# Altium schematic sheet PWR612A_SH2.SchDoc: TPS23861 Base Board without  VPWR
size 558 x 431 mm; Engineer: Trevor; Revision: A; Name: Trevor
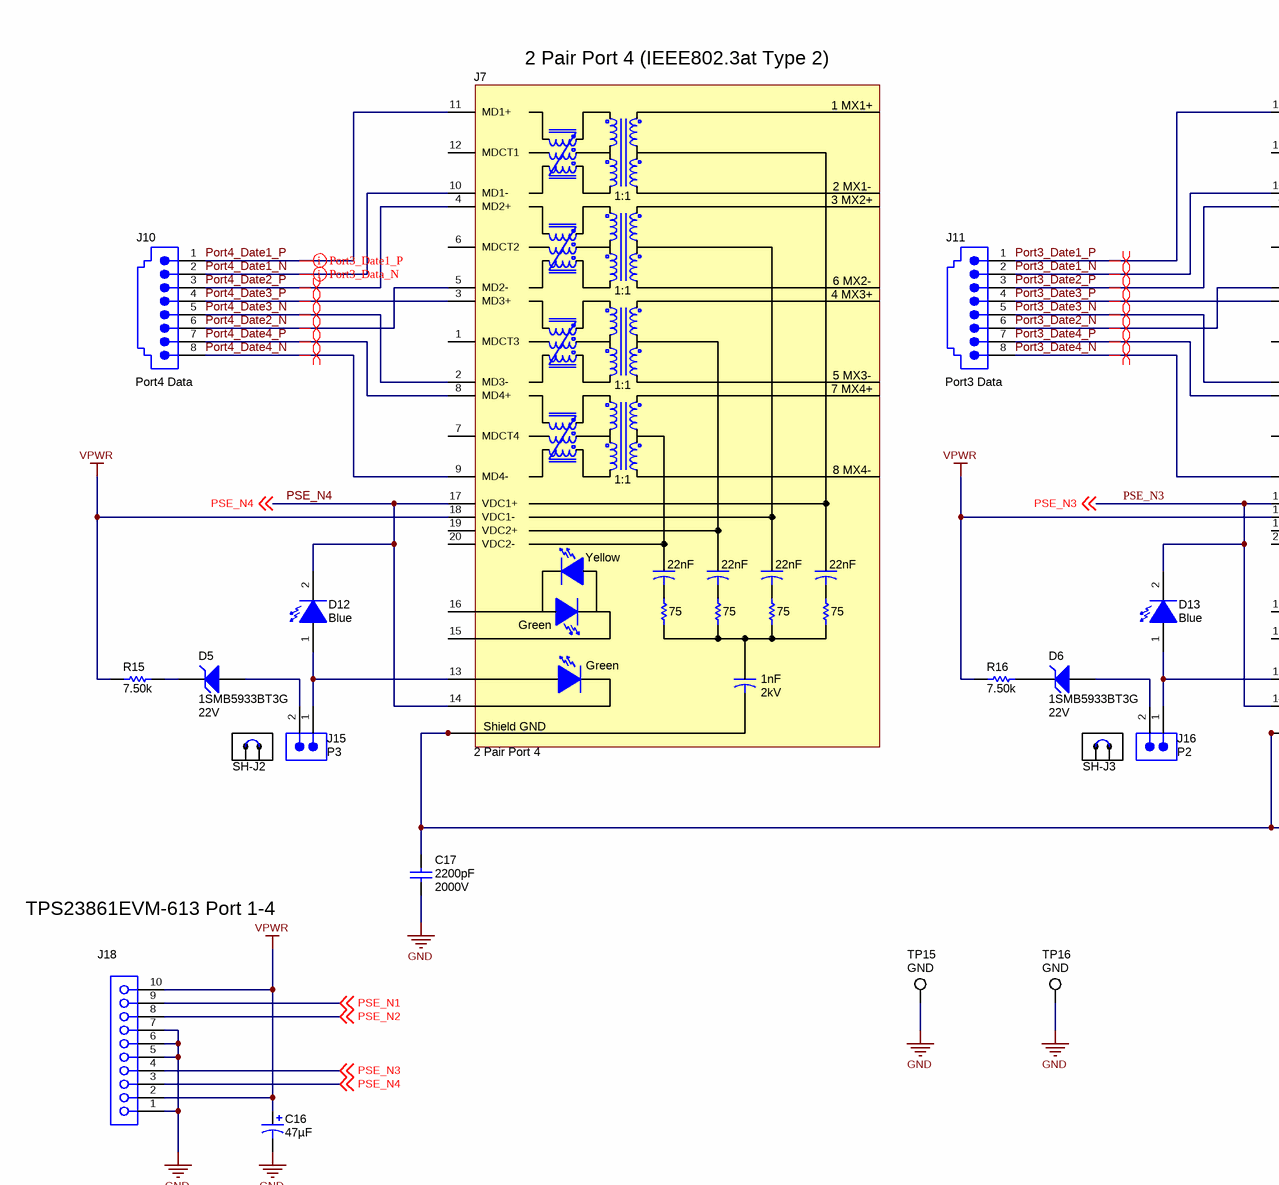
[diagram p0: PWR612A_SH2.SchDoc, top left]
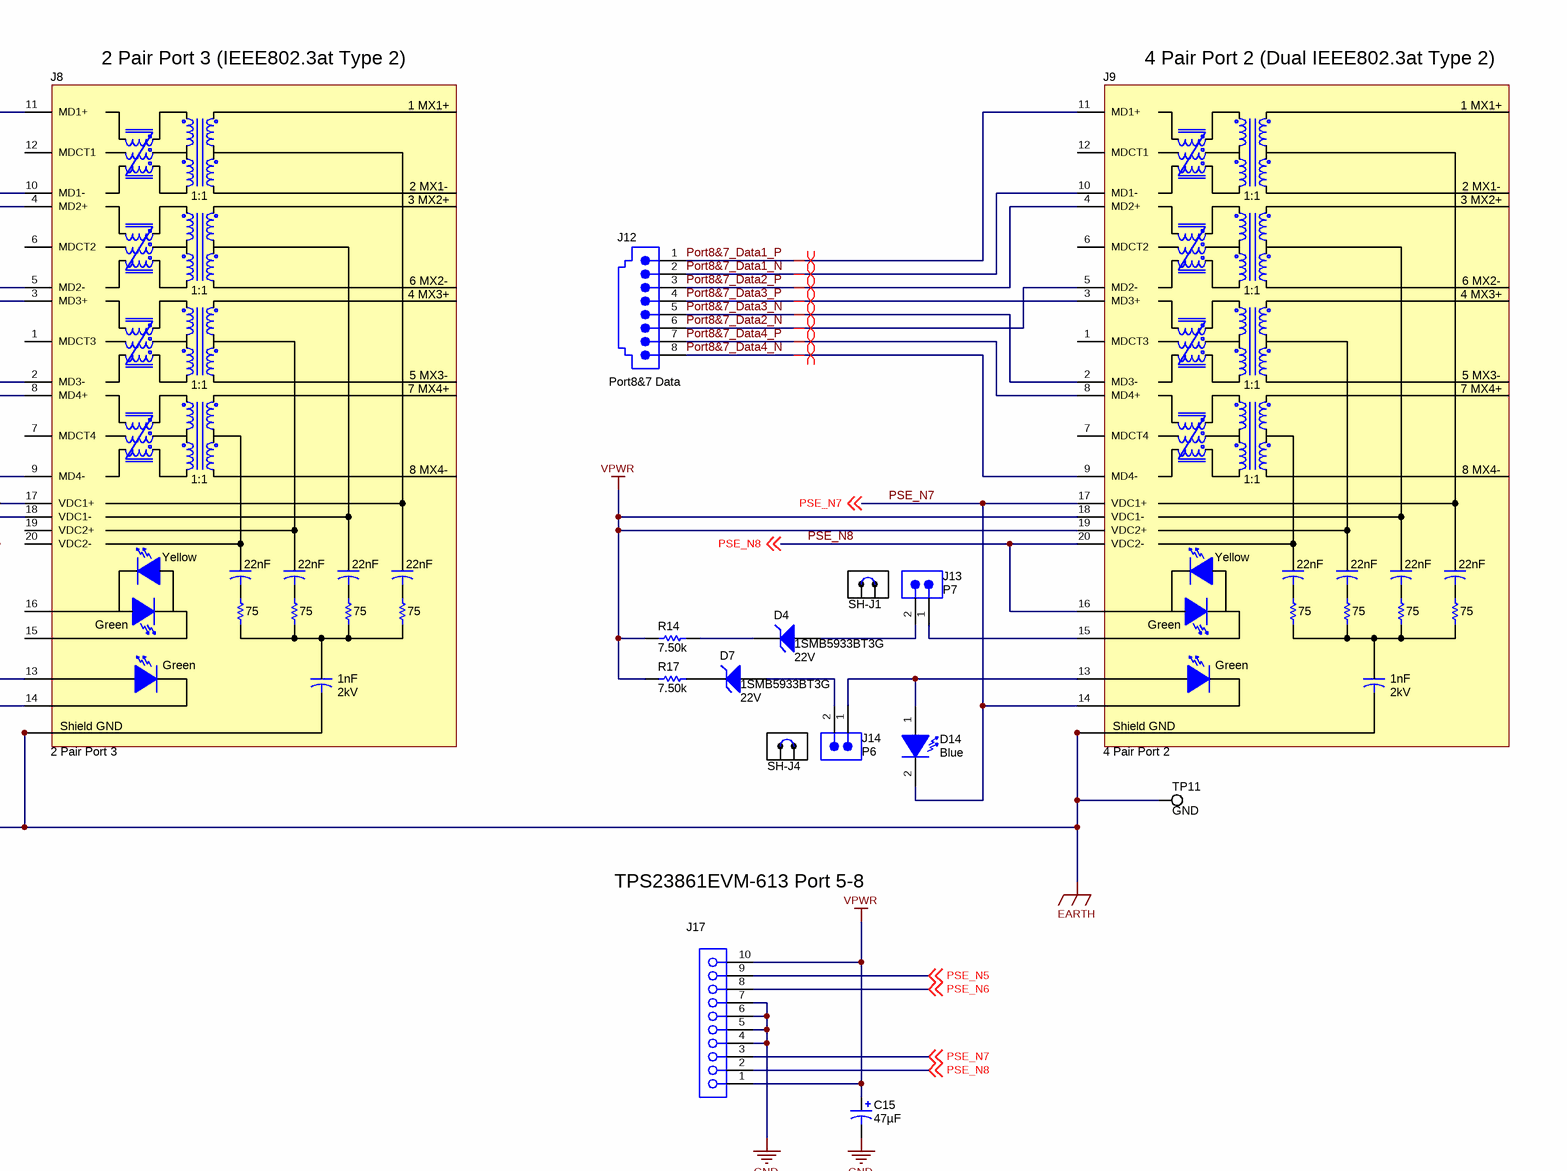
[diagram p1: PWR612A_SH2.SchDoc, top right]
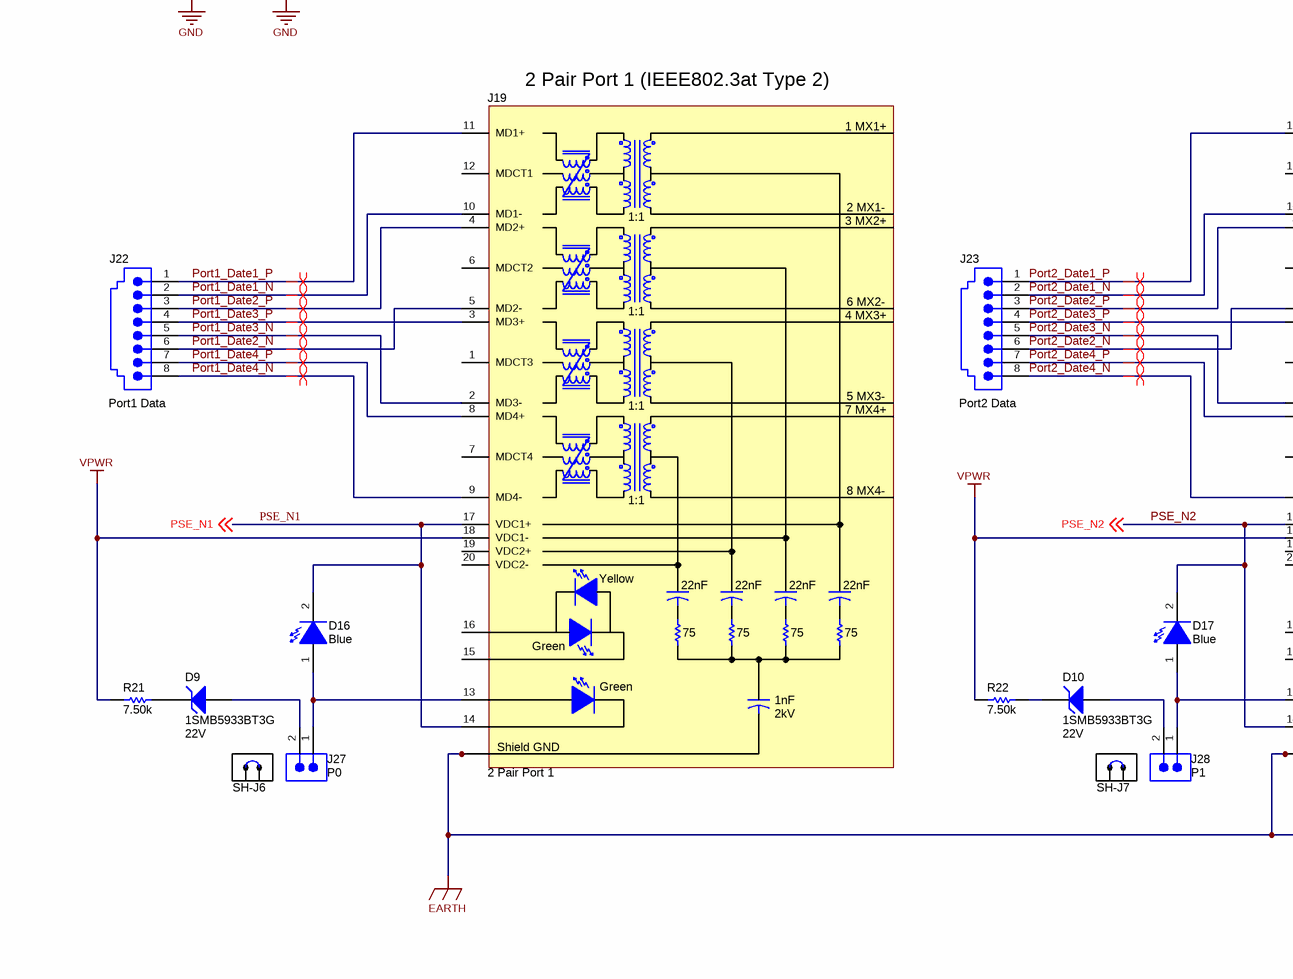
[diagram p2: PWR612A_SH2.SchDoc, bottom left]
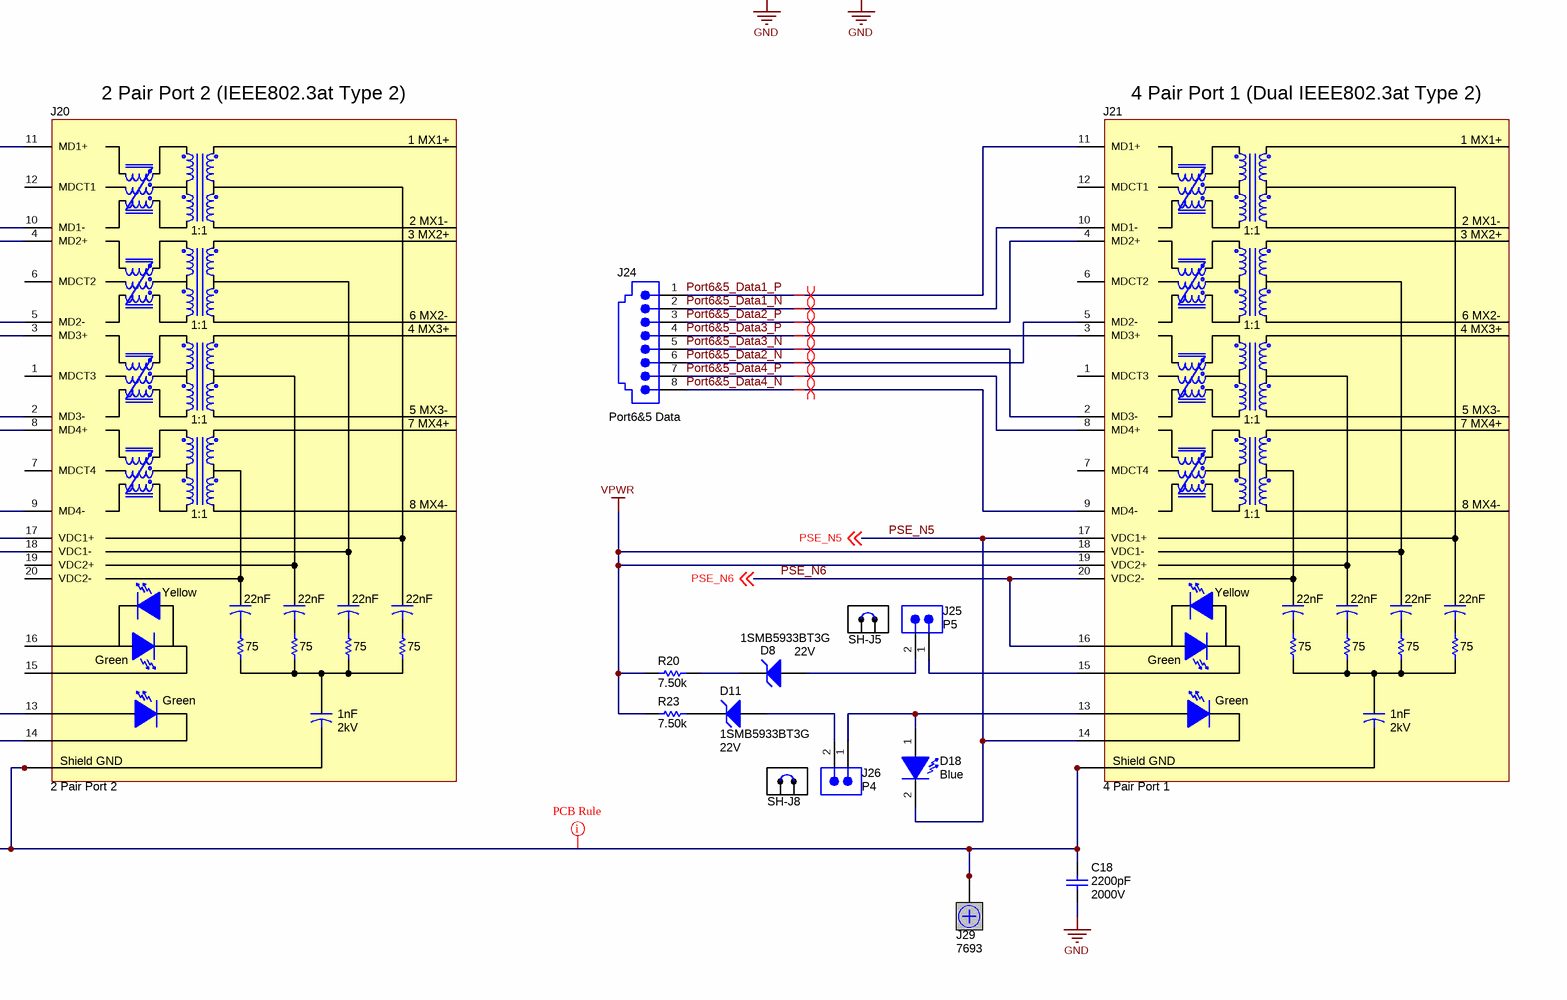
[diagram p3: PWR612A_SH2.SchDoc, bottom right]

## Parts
C15  ValueDisplayed: 47µF  [SM_RADIAL_H13]  (hidden comment: EEV-FK2A470Q)
C16  ValueDisplayed: 47µF  [SM_RADIAL_H13]  (hidden comment: EEV-FK2A470Q)
C17  ValueDisplayed: 2200pF  Value2: 2000V  [1812]  (hidden comment: C4532X7R3D222K)
C18  ValueDisplayed: 2200pF  Value2: 2000V  [1812]  (hidden comment: C4532X7R3D222K)
D4  1SMB5933BT3G  value 22V  [SMB]
D5  1SMB5933BT3G  value 22V  [SMB]
D6  1SMB5933BT3G  value 22V  [SMB]
D7  1SMB5933BT3G  value 22V  [SMB]
D8  1SMB5933BT3G  value 22V  [SMB]
D9  1SMB5933BT3G  value 22V  [SMB]
D10  1SMB5933BT3G  value 22V  [SMB]
D11  1SMB5933BT3G  value 22V  [SMB]
D12  value Blue  [LB Q39G_BLUE]  (hidden comment: LB Q39G-L2N2-35-1)
D13  value Blue  [LB Q39G_BLUE]  (hidden comment: LB Q39G-L2N2-35-1)
D14  value Blue  [LB Q39G_BLUE]  (hidden comment: LB Q39G-L2N2-35-1)
D16  value Blue  [LB Q39G_BLUE]  (hidden comment: LB Q39G-L2N2-35-1)
D17  value Blue  [LB Q39G_BLUE]  (hidden comment: LB Q39G-L2N2-35-1)
D18  value Blue  [LB Q39G_BLUE]  (hidden comment: LB Q39G-L2N2-35-1)
J7  2 Pair Port 4  [JK0-0177NL]
J8  2 Pair Port 3  [JK0-0177NL]
J9  4 Pair Port 2  [JK0-0177NL]
J10  SS-7188V-A-NF  [CONN_SS-7188V-A-NF]  (value not drawn)
J11  SS-7188V-A-NF  [CONN_SS-7188V-A-NF]  (value not drawn)
J12  SS-7188V-A-NF  [CONN_SS-7188V-A-NF]  (value not drawn)
J13  P7  [TSW-102-07-G-S]
J14  P6  [TSW-102-07-G-S]
J15  P3  [TSW-102-07-G-S]
J16  P2  [TSW-102-07-G-S]
J17  Port8&7&6&5  [CONN_SSW-110-23-F-S]  (value not drawn)
J18  Port4&3&2&1  [CONN_SSW-110-23-F-S]  (value not drawn)
J19  2 Pair Port 1  [JK0-0177NL]
J20  2 Pair Port 2  [JK0-0177NL]
J21  4 Pair Port 1  [JK0-0177NL]
J22  SS-7188V-A-NF  [CONN_SS-7188V-A-NF]  (value not drawn)
J23  SS-7188V-A-NF  [CONN_SS-7188V-A-NF]  (value not drawn)
J24  SS-7188V-A-NF  [CONN_SS-7188V-A-NF]  (value not drawn)
J25  P5  [TSW-102-07-G-S]
J26  P4  [TSW-102-07-G-S]
J27  P0  [TSW-102-07-G-S]
J28  P1  [TSW-102-07-G-S]
J29  7693  [7693]
R14  value 7.50k  [1206]  (hidden comment: CRCW12067K50FKEA)
R15  value 7.50k  [1206]  (hidden comment: CRCW12067K50FKEA)
R16  value 7.50k  [1206]  (hidden comment: CRCW12067K50FKEA)
R17  value 7.50k  [1206]  (hidden comment: CRCW12067K50FKEA)
R20  value 7.50k  [1206]  (hidden comment: CRCW12067K50FKEA)
R21  value 7.50k  [1206]  (hidden comment: CRCW12067K50FKEA)
R22  value 7.50k  [1206]  (hidden comment: CRCW12067K50FKEA)
R23  value 7.50k  [1206]  (hidden comment: CRCW12067K50FKEA)
SH-J1  SPC02SYAN  [SPC02SYAN]  (value not drawn)
SH-J2  SPC02SYAN  [SPC02SYAN]  (value not drawn)
SH-J3  SPC02SYAN  [SPC02SYAN]  (value not drawn)
SH-J4  SPC02SYAN  [SPC02SYAN]  (value not drawn)
SH-J5  SPC02SYAN  [SPC02SYAN]  (value not drawn)
SH-J6  SPC02SYAN  [SPC02SYAN]  (value not drawn)
SH-J7  SPC02SYAN  [SPC02SYAN]  (value not drawn)
SH-J8  SPC02SYAN  [SPC02SYAN]  (value not drawn)
TP11  GND  [Testpoint_Keystone_Compact]
TP15  GND  [Testpoint_Keystone_Compact]
TP16  GND  [Testpoint_Keystone_Compact]

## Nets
EARTH: C17.1 C18.1 J7.21(Shield) J7.22(Shield) J8.21(Shield) J8.22(Shield) J9.21(Shield) J9.22(Shield) J19.21(Shield) J19.22(Shield) J20.21(Shield) J20.22(Shield) J21.21(Shield) J21.22(Shield) J29.1 J29.2 J29.3 J29.4 TP11.1
GND: C15.2(-) C16.2(-) C17.2 C18.2 J17.4 J17.5 J17.6 J17.7 J18.1 J18.5 J18.6 J18.7 TP15.1 TP16.1
VPWR: C15.1(+) C16.1(+) J7.18(VDC1-) J8.18(VDC1-) J9.18(VDC1-) J9.19(VDC2+) J17.1 J17.10 J18.2 J18.10 J19.18(VDC1-) J20.18(VDC1-) J21.18(VDC1-) J21.19(VDC2+) R14.1 R15.1 R16.1 R17.1 R20.1 R21.1 R22.1 R23.1
Port1_Date1_N: J19.10(MD1-) J22.2
Port1_Date1_P: J19.11(MD1+) J22.1
Port1_Date2_N: J19.5(MD2-) J22.6
Port1_Date2_P: J19.4(MD2+) J22.3
Port1_Date3_N: J19.2(MD3-) J22.5
Port1_Date3_P: J19.3(MD3+) J22.4
Port1_Date4_N: J19.9(MD4-) J22.8
Port1_Date4_P: J19.8(MD4+) J22.7
Port2_Date1_N: J20.10(MD1-) J23.2
Port2_Date1_P: J20.11(MD1+) J23.1
Port2_Date2_N: J20.5(MD2-) J23.6
Port2_Date2_P: J20.4(MD2+) J23.3
Port2_Date3_N: J20.2(MD3-) J23.5
Port2_Date3_P: J20.3(MD3+) J23.4
Port2_Date4_N: J20.9(MD4-) J23.8
Port2_Date4_P: J20.8(MD4+) J23.7
Port3_Date1_N: J8.10(MD1-) J11.2
Port3_Date1_P: J8.11(MD1+) J11.1
Port3_Date2_N: J8.5(MD2-) J11.6
Port3_Date2_P: J8.4(MD2+) J11.3
Port3_Date3_N: J8.2(MD3-) J11.5
Port3_Date3_P: J8.3(MD3+) J11.4
Port3_Date4_N: J8.9(MD4-) J11.8
Port3_Date4_P: J8.8(MD4+) J11.7
Port4_Date1_N: J7.10(MD1-) J10.2
Port4_Date1_P: J7.11(MD1+) J10.1
Port4_Date2_N: J7.5(MD2-) J10.6
Port4_Date2_P: J7.4(MD2+) J10.3
Port4_Date3_N: J7.2(MD3-) J10.5
Port4_Date3_P: J7.3(MD3+) J10.4
Port4_Date4_N: J7.9(MD4-) J10.8
Port4_Date4_P: J7.8(MD4+) J10.7
Port6&5_Data1_N: J21.10(MD1-) J24.2
Port6&5_Data1_P: J21.11(MD1+) J24.1
Port6&5_Data2_N: J21.5(MD2-) J24.6
Port6&5_Data2_P: J21.4(MD2+) J24.3
Port6&5_Data3_N: J21.2(MD3-) J24.5
Port6&5_Data3_P: J21.3(MD3+) J24.4
Port6&5_Data4_N: J21.9(MD4-) J24.8
Port6&5_Data4_P: J21.8(MD4+) J24.7
Port8&7_Data1_N: J9.10(MD1-) J12.2
Port8&7_Data1_P: J9.11(MD1+) J12.1
Port8&7_Data2_N: J9.5(MD2-) J12.6
Port8&7_Data2_P: J9.4(MD2+) J12.3
Port8&7_Data3_N: J9.2(MD3-) J12.5
Port8&7_Data3_P: J9.3(MD3+) J12.4
Port8&7_Data4_N: J9.9(MD4-) J12.8
Port8&7_Data4_P: J9.8(MD4+) J12.7
PSE_N1: D16.2(K) J18.9 J19.14 J19.17(VDC1+) ; off-sheet PSE_N1
PSE_N2: D17.2(K) J18.8 J20.14 J20.17(VDC1+) ; off-sheet PSE_N2
PSE_N3: D13.2(K) J8.14 J8.17(VDC1+) J18.4 ; off-sheet PSE_N3
PSE_N4: D12.2(K) J7.14 J7.17(VDC1+) J18.3 ; off-sheet PSE_N4
PSE_N5: D18.2(K) J17.9 J21.14 J21.17(VDC1+) ; off-sheet PSE_N5
PSE_N6: J17.8 J21.16 J21.20(VDC2-) ; off-sheet PSE_N6
PSE_N7: D14.2(K) J9.14 J9.17(VDC1+) J17.3 ; off-sheet PSE_N7
PSE_N8: J9.16 J9.20(VDC2-) J17.2 ; off-sheet PSE_N8
NetD4_1: D4.1(K) R14.2
NetD4_2: D4.2(A) J13.2
NetD5_1: D5.1(K) R15.2
NetD5_2: D5.2(A) J15.2
NetD6_1: D6.1(K) R16.2
NetD6_2: D6.2(A) J16.2
NetD7_1: D7.1(K) R17.2
NetD7_2: D7.2(A) J14.2
NetD8_1: D8.1(K) R20.2
NetD8_2: D8.2(A) J25.2
NetD9_1: D9.1(K) R21.2
NetD9_2: D9.2(A) J27.2
NetD10_1: D10.1(K) R22.2
NetD10_2: D10.2(A) J28.2
NetD11_1: D11.1(K) R23.2
NetD11_2: D11.2(A) J26.2
NetD12_1: D12.1(A) J7.13 J15.1
NetD13_1: D13.1(A) J8.13 J16.1
NetD14_1: D14.1(A) J9.13 J14.1
NetD16_1: D16.1(A) J19.13 J27.1
NetD17_1: D17.1(A) J20.13 J28.1
NetD18_1: D18.1(A) J21.13 J26.1
NetJ9_15: J9.15 J13.1
NetJ21_15: J21.15 J25.1

Not connected (* = marked no-connect by the designer): J7 1(MDCT3) 6(MDCT2) 7(MDCT4) 12(MDCT1) 15 16 19(VDC2+) 20(VDC2-); J8 1(MDCT3) 6(MDCT2) 7(MDCT4) 12(MDCT1) 15 16 19(VDC2+) 20(VDC2-); J9 1(MDCT3) 6(MDCT2) 7(MDCT4) 12(MDCT1); J19 1(MDCT3) 6(MDCT2) 7(MDCT4) 12(MDCT1) 15 16 19(VDC2+) 20(VDC2-); J20 1(MDCT3) 6(MDCT2) 7(MDCT4) 12(MDCT1) 15 16 19(VDC2+) 20(VDC2-); J21 1(MDCT3) 6(MDCT2) 7(MDCT4) 12(MDCT1)

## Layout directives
differential pair: Port1_Date1_N, Port1_Date1_P, Port1_Date2_N, Port1_Date2_P, Port1_Date3_N, Port1_Date3_P, Port1_Date4_N, Port1_Date4_P, Port2_Date1_N, Port2_Date1_P, Port2_Date2_N, Port2_Date2_P, Port2_Date3_N, Port2_Date3_P, Port2_Date4_N, Port2_Date4_P, Port3_Date1_N, Port3_Date1_P, Port3_Date2_N, Port3_Date2_P, Port3_Date3_N, Port3_Date3_P, Port3_Date4_N, Port3_Date4_P, Port4_Date1_N, Port4_Date1_P, Port4_Date2_N, Port4_Date2_P, Port4_Date3_N, Port4_Date3_P, Port4_Date4_N, Port4_Date4_P, Port6&5_Data1_N, Port6&5_Data1_P, Port6&5_Data2_N, Port6&5_Data2_P, Port6&5_Data3_N, Port6&5_Data3_P, Port6&5_Data4_N, Port6&5_Data4_P, Port8&7_Data1_N, Port8&7_Data1_P, Port8&7_Data2_N, Port8&7_Data2_P, Port8&7_Data3_N, Port8&7_Data3_P, Port8&7_Data4_N, Port8&7_Data4_P
rule Undefined; rule Clearance Constraint [Clearance = 39mil]: EARTH

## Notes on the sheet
- 2 Pair Port 4 (IEEE802.3at Type 2)
- 2 Pair Port 3 (IEEE802.3at Type 2)
- (near J9) 4 Pair Port 2 (Dual IEEE802.3at Type 2)
- (near J10) Port4 Data
- (near J11) Port3 Data
- (near J12) Port8&7 Data
- TPS23861EVM-613 Port 1-4
- TPS23861EVM-613 Port 5-8
- (near J19) 2 Pair Port 1 (IEEE802.3at Type 2)
- 2 Pair Port 2 (IEEE802.3at Type 2)
- (near J21) 4 Pair Port 1 (Dual IEEE802.3at Type 2)
- (near J22) Port1 Data
- (near J23) Port2 Data
- (near J24) Port6&5 Data

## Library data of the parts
C15 C16 = EEV-FK2A470Q: CAP, AL, 47uF, 100V, +/-20%, 0.32 ohm, SMD; Manufacturer: Panasonic; Polarized: Y; CompType: Capacitor; U/M: EA; Cap_F: 0.000047; Tolerance_%: 20; VDC_V: 100; ESR_Ohm: 0.32; IRMS_A: 0.5; TaMin_C: -55; TaMax_C: 105; Cap_Case: H13
C17 C18 = C4532X7R3D222K: CAP, CERM, 2200pF, 2000V, +/-10%, X7R, 1812; Manufacturer: TDK; Polarized: N; CompType: Capacitor; U/M: EA; Cap_F: 0.0000000022; Tolerance_%: 10; Value1: Unknown; VDC_V: 2000; TaMin_C: -55; TaMax_C: 125
D4-D11 = 1SMB5933BT3G: Diode, Zener, 22V, 550mW, SMB; Manufacturer: ON Semiconductor; U/M: EA; Power_W: 0.55; Vz_V: 22; Value1: 0.55W; RJA_CperW: 226
D12-D14 D16-D18 = LB Q39G-L2N2-35-1: LED, Blue, SMD; Manufacturer: OSRAM; Vf_V: 2.85; Value2: 2.85V; Io_A: 0.15; Tjmax_C: 95; Value1: W; U/M: EA
J7-J9 J19-J21 = JK0-0177NL: RJ-45 with integrated magnetics; Manufacturer: Pulse Engineering; Alternate Manufacturer: Wurth Elektronik; Alternate PartNumber: 7499511611 or 7499511611A; SymbolCreator: x0208325; CompType: Connector; U/M: EA
J10-J12 J22-J24 = SS-7188V-A-NF: RJ-45, Vertical, TH; Manufacturer: Stewart Connector; SymbolCreator: a0799628; CompType: Connector; U/M: EA
J13-J16 J25-J28 = TSW-102-07-G-S: Header, TH, 100mil, 2x1, Gold plated, 230 mil above insulator; Manufacturer: Samtec, Inc.; SymbolCreator: a0412235; U/M: EA
J17 J18 = SSW-110-23-F-S: Connector, Receptacle, 100mil, 10x1, Gold plated, TH; PartNumber: SSW-110-01-G-S; Manufacturer: Samtec, Inc.; SymbolCreator: a0411947; U/M: EA
J29 = 7693: Terminal screw, vertical, snap-in; Manufacturer: Keystone; SymbolCreator: a0412235; Value: 15A; CompType: Screw Terminal; U/M: EA
R14-R17 R20-R23 = CRCW12067K50FKEA: RES, 7.50k ohm, 1%, 0.25W, 1206; Manufacturer: Vishay-Dale; CompType: Resistor; Res_ohm: 7500; Value_Code: 7k50; Tolerance_%: 1; Power_W: 0.25; VDC_V: 200; TempCo: 100 ppm/C; EIA_Code: E96; U/M: EA
SH-J1-SH-J8 = SPC02SYAN: Shunt, 100mil, Flash Gold, Black; Manufacturer: Sullins Connector Solutions; Value: 1x2; Note: You can "mate" this to a header by matching the designator.  i.e. use SH-J3 for header J3
TP11 TP15 TP16 = 5016: Test Point, Compact, SMT; Manufacturer: Keystone; CompType: Test Point Loop; U/M: EA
